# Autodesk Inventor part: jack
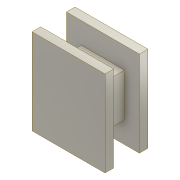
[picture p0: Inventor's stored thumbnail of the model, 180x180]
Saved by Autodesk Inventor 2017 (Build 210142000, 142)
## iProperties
Part Number: jack
Material: チタン
Document SubType Name: Modeling
Designer: kyushu-hep
Density: 4.51 g/cm^3
Appearance: チタン
Author: kyushu-hep
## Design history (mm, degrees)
sketch "スケッチ1"
  geometry: L1 (-25, 25)-(25, 25); L2 (25, 25)-(25, -25); L3 (25, -25)-(-25, -25); L4 (-25, -25)-(-25, 25); L5 (-25, 25)-(25, -25); L6 (25, 25)-(-25, -25); 1 further point
  constraints: 12 end point, 2 midpoint, 2 parallel, 1 horizontal, 1 perpendicular
  dimensions: "d8" = 50 distance of L3.end L1.start; "d9" = 50 distance of L1.start L1.end
extrude "押し出し1" new body sketch "スケッチ1" distance "d0" = 30; taper "d1" = 0 deg
sketch "スケッチ2"
  geometry: L1 (42.5, 50)-(-42.5, 50); L2 (-42.5, 50)-(-42.5, -50); L3 (-42.5, -50)-(42.5, -50); L4 (42.5, -50)-(42.5, 50); L5 (42.5, 50)-(-42.5, -50); L6 (-42.5, 50)-(42.5, -50); 1 further point
  constraints: 12 end point, 2 midpoint, 2 parallel, 1 horizontal, 1 perpendicular
  dimensions: "d2" = 85 distance of L3.end L2.end; "d3" = 100 distance of L2.end L1.end
extrude "押し出し2" join sketch "スケッチ2" distance "d4" = 10; taper "d5" = 0 deg
sketch "スケッチ3"
  geometry: L1 (42.5, 50)-(-42.5, 50); L2 (-42.5, 50)-(-42.5, -50); L3 (-42.5, -50)-(42.5, -50); L4 (42.5, -50)-(42.5, 50); 1 further point
  constraints: 8 end point, 2 parallel, 1 horizontal, 1 perpendicular
extrude "押し出し3" join sketch "スケッチ3" distance "d6" = 10; taper "d7" = 0 deg
node "ソリッド1"
